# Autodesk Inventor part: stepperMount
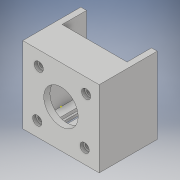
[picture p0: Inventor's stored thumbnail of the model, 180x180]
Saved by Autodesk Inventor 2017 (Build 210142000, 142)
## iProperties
Created: 2017-04
Part Number: stepperMount
Material: Generic
Document SubType Name: Modeling
Designer: Andres Celi
Density: 1 g/cm^3
Appearance: Default
Author: Andres Celi
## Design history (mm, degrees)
sketch "Sketch1"
  geometry: 1 further point
sketch "Sketch2"
  geometry: L1 (-25, 25)-(25, 25); L2 (25, 25)-(25, -25); L3 (25, -25)-(-25, -25); L4 (-25, -25)-(-25, 25); 1 further point
  constraints: 8 end point, 2 parallel, 1 horizontal, 1 perpendicular
  dimensions: "d0" = 50 distance of L2.end L3.end; "d1" = 50 distance of L1.end L2.end; "d2" = 25 distance from line of L4 point (0, 0); "d3" = 25 distance from line of point (0, 0) L1
extrude "Extrusion1" new body sketch "Sketch2" distance "d4" = 38; taper "d5" = 0 deg
sketch "Sketch3"
  geometry: 1 further point
sketch "Sketch4"
  geometry: L1 (0, 0)-(50, 0) reference; L2 (46.25, 0)-(3.75, 0); L3 (3.75, 0)-(3.75, -16); L4 (3.75, -16)-(46.25, -16); L5 (46.25, -16)-(46.25, 0); L6 (50, 0)-(50, -38) reference; 1 further point
  constraints: 8 end point, 2 parallel, 1 horizontal, 1 perpendicular, 1 point on line
  dimensions: "d6" = 42.5 distance of L4.end L3.end; "d7" = 16 distance of L3.end L2.end; "d8" = 3.75 distance between parallel lines of L6 L5
extrude "Extrusion2" cut sketch "Sketch4" distance "d9" = 46.25; taper "d10" = 0 deg
sketch "Sketch5"
  geometry: L1 (0, -46.25)-(0, 0) reference; L2 (42.5, 0)-(42.5, -46.25) reference; L3 (0, -3.75)-(42.5, -3.75); L4 (42.5, -3.75)-(42.5, -46.25); L5 (42.5, -46.25)-(0, -46.25); L6 (0, -46.25)-(0, -3.75); L7 (-3.75, 0)-(46.25, 0) reference; 1 further point
  constraints: 8 end point, 2 parallel, 1 horizontal, 1 perpendicular, 1 point on line
  dimensions: "d11" = 3.75 distance between parallel lines of L7 L3
extrude "Extrusion3" cut sketch "Sketch5" distance "d12" = 18; taper "d13" = 0 deg
sketch "Sketch6"
  geometry: 1 further point
sketch "Sketch7"
  geometry: C1 r 11.25 at (0, 0); 1 further point
  constraints: 1 centre point, 1 coincident
  dimensions: "d14" = 22.5 diameter of C1
extrude "Extrusion4" cut sketch "Sketch7" distance "d15" = 6; taper "d16" = 0 deg
sketch "Sketch8"
  geometry: C1 r 1.625 at (-14.51, 15.5); C2 r 1.625 at (16.49, 15.5); C3 r 1.625 at (15.5, -15.5); C4 r 1.625 at (-15.5, -15.5); 1 further point
  constraints: 4 centre point
  dimensions: "d17" = 3.25 diameter of C1; "d18" = 3.25 diameter of C2; "d19" = 3.25 diameter of C3; "d20" = 3.25 diameter of C4; "d21" = 15.5 vertical distance of point (0, 0) C1.centre; "d22" = 31 vertical distance of C3.centre C2.centre; "d23" = 31 distance of C1.centre C2.centre; "d24" = 15.5 vertical distance of point (0, 0) C2.centre; "d25" = 31 distance of C4.centre C3.centre; "d26" = 15.5 horizontal distance of point (0, 0) C4.centre; "d27" = 15.5 horizontal distance of point (0, 0) C4.centre
extrude "Extrusion5" cut sketch "Sketch8" distance "d28" = 4; taper "d29" = 0 deg
sketch "Sketch9"
  geometry: 1 further point
sketch "Sketch10"
  geometry: L1 (37.5, 6.902)-(37.5, 27.098); L2 (46.25, 34)-(3.75, 34) reference; L3 (39.125, 6.902)-(39.125, 27.098); L4 (35.875, 27.098)-(35.875, 6.902); L5 (12.5, 6.902)-(12.5, 27.098); L6 (14.125, 6.902)-(14.125, 27.098); L7 (10.875, 27.098)-(10.875, 6.902); L8 (50, 0)-(0, 0) reference; L9 (0, 0)-(0, 38) reference; A1 r 1.625 centre (37.5, 6.902) between (35.875, 6.902) and (39.125, 6.902); A2 r 1.625 centre (37.5, 27.098) between (39.125, 27.098) and (35.875, 27.098); A3 r 1.625 centre (12.5, 6.902) between (10.875, 6.902) and (14.125, 6.902); A4 r 1.625 centre (12.5, 27.098) between (14.125, 27.098) and (10.875, 27.098); 3 further points
  constraints: 16 end point, 8 point on circle, 8 tangent, 4 centre point, 3 parallel, 2 midpoint, 1 perpendicular
  dimensions: "d30" = 3.25 diameter of A2; "d31" = 3.25 diameter of A4; "d32" = 17 distance from line of L8 point (37.5, 17); "d33" = 17 distance from line of L8 point (12.5, 17); "d34" = 25 distance of point (12.5, 17) point (37.5, 17); "d35" = 12.5 distance from line of L9 point (12.5, 17)
extrude "Extrusion6" cut sketch "Sketch10" distance "d36" = 4; taper "d37" = 0 deg
sketch "Sketch11"
  geometry: 1 further point
sketch "Sketch12"
  geometry: C1 r 1.625 at (-14.51, 15.5) reference; C2 r 3 at (-14.51, 15.5); C3 r 1.625 at (16.49, 15.5) reference; C4 r 3 at (16.49, 15.5); C5 r 1.625 at (-15.5, -15.5) reference; C6 r 3 at (-15.5, -15.5); C7 r 1.625 at (15.5, -15.5) reference; C8 r 3 at (15.5, -15.5); 1 further point
  constraints: 4 centre point, 4 coincident
  dimensions: "d38" = 6 diameter of C2; "d39" = 6 diameter of C4; "d40" = 6 diameter of C6; "d41" = 6 diameter of C8
extrude "Extrusion7" cut sketch "Sketch12" distance "d42" = 2; taper "d43" = 0 deg
sketch "Sketch13"
  geometry: L1 (12.5, -27.098)-(12.5, -6.902); L2 (15.5, -27.098)-(15.5, -6.902); L3 (9.5, -6.902)-(9.5, -27.098); L4 (37.5, -27.098)-(37.5, -6.902); L5 (40.5, -27.098)-(40.5, -6.902); L6 (34.5, -6.902)-(34.5, -27.098); A1 r 1.625 centre (12.5, -27.098) between (10.875, -27.098) and (14.125, -27.098) reference; A2 r 1.625 centre (12.5, -6.902) between (14.125, -6.902) and (10.875, -6.902) reference; A3 r 3 centre (12.5, -27.098) between (9.5, -27.098) and (15.5, -27.098); A4 r 3 centre (12.5, -6.902) between (15.5, -6.902) and (9.5, -6.902); A5 r 1.625 centre (37.5, -27.098) between (35.875, -27.098) and (39.125, -27.098) reference; A6 r 1.625 centre (37.5, -6.902) between (39.125, -6.902) and (35.875, -6.902) reference; A7 r 3 centre (37.5, -27.098) between (34.5, -27.098) and (40.5, -27.098); A8 r 3 centre (37.5, -6.902) between (40.5, -6.902) and (34.5, -6.902); 3 further points
  constraints: 16 end point, 8 point on circle, 8 tangent, 4 centre point, 3 parallel, 2 midpoint, 1 vertical
  dimensions: "d44" = 6 diameter of A4; "d45" = 6 diameter of A8
extrude "Extrusion8" cut sketch "Sketch13" distance "d46" = 2; taper "d47" = 0 deg
body "Solid1"
